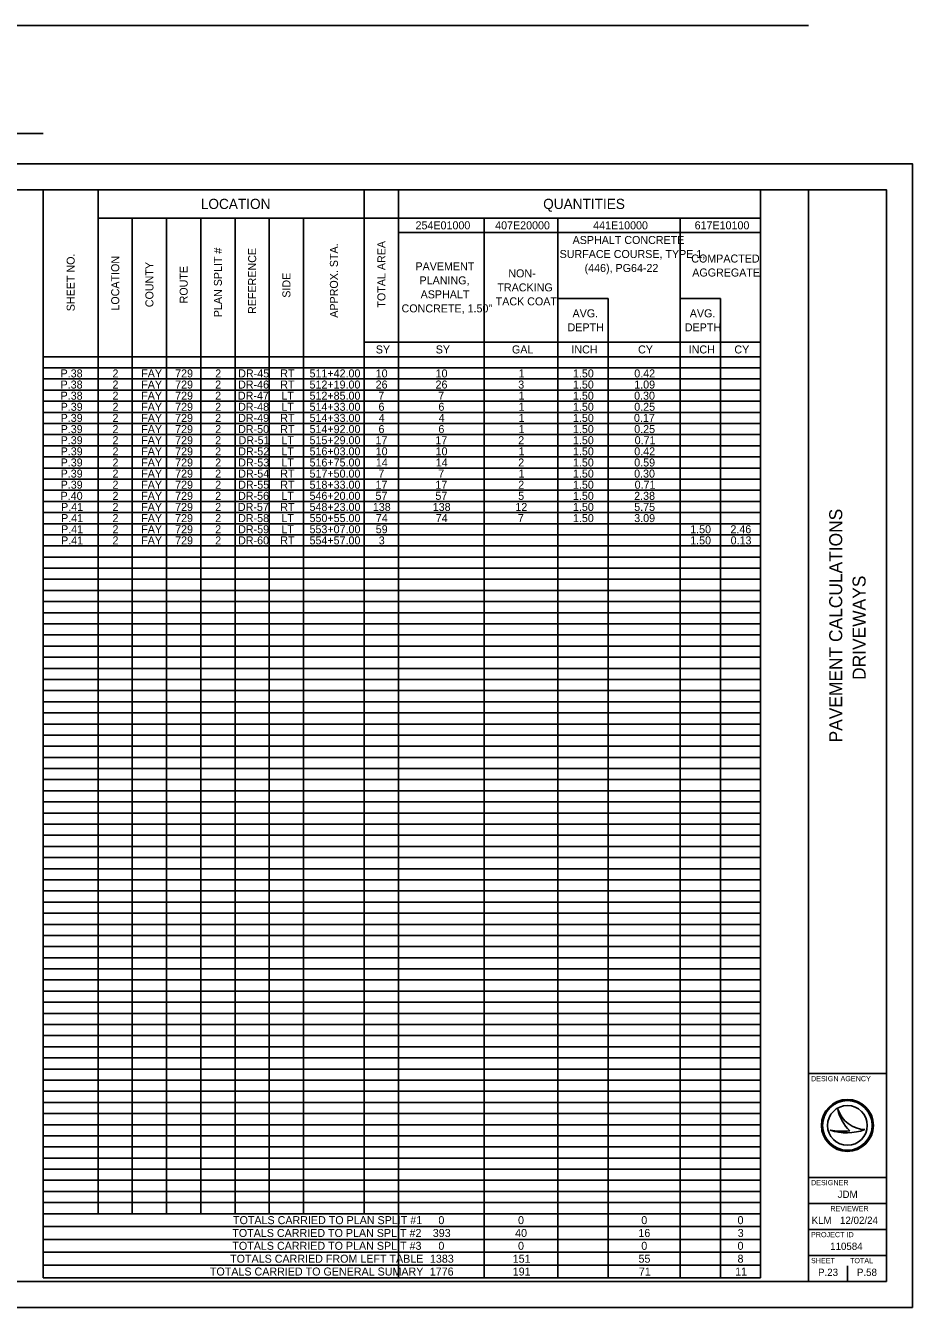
# Model space of a CAD drawing. Extents: x 0 to 34, y 0 to 24.7.
# Drawn here: x 16.94 to 34, y 0 to 24.66 of the extents above; entities that cross this region are included whole.
import ezdxf

# ---------------------------------------------------------------- set-up
doc = ezdxf.new("R2010")
doc.units = 0
for name, color, linetype in [('SH_Border', 7, 'Continuous'), ('SH_Cut_Line', 7, 'Continuous'), ('SH_Data', 7, 'Continuous'), ('SH_Text', 7, 'Continuous')]:
    doc.layers.add(name, color=color, linetype=linetype)

msp = doc.modelspace()

# ---------------------------------------------------------------- linework, layer by layer
at = {"layer": 'SH_Border'}
for p, q in [((32, 0.5), (32, 21.5)), ((32, 4.5), (33.5, 4.5)), ((32, 2.5), (33.5, 2.5)), ((32, 2), (33.5, 2)), ((32, 1.5), (33.5, 1.5)), ((32, 1), (33.5, 1))]:
    msp.add_line(p, q, dxfattribs=at)
msp.add_lwpolyline([(1.5, 21.5), (33.5, 21.5), (33.5, 0.5), (1.5, 0.5)], close=True, dxfattribs=at)
at = {"layer": 'SH_Cut_Line'}
msp.add_lwpolyline([(0, 0), (34, 0), (34, 22), (0, 22)], close=True, dxfattribs=at)
at = {"layer": 'SH_Data'}
for p, q in [((32.567, 3.81), (32.567, 3.81)), ((32.75, 3.5), (32.75, 3.5)), ((32.417, 3.41), (32.417, 3.41)), ((33.087, 3.419), (33.087, 3.419)), ((32.75, 0.5), (32.75, 0.8)), ((32.375, 0.675), (32.375, 0.675))]:
    msp.add_line(p, q, dxfattribs=at)
for radius in [0.5, 0.477, 0.477, 0.382]:
    msp.add_circle((32.75, 3.5), radius, dxfattribs=at)
for centre, radius, start, end in [((33.116, 3.998), 0.58, 198.9257, 198.9319), ((33.347, 3.97), 0.796, 191.6379, 191.6421), ((33.116, 3.998), 0.58, 198.9319, 267.1657), ((33.347, 3.97), 0.796, 191.6421, 226.0947), ((32.739, 4.37), 1.013, 251.4576, 290.0832), ((32.648, 4.654), 1.266, 259.4964, 259.4995), ((32.739, 4.37), 1.013, 251.4527, 251.4576), ((32.648, 4.654), 1.266, 259.4995, 276.6672)]:
    msp.add_arc(centre, radius, start, end, dxfattribs=at)
at = {"layer": 'SH_Text'}
for p, q in [((1.5, 24.657), (32, 24.657)), ((16.223, 22.58), (17.277, 22.58)), ((17.277, 21.5), (31.079, 21.5)), ((17.277, 21.5), (17.277, 0.566)), ((18.331, 21.5), (18.331, 1.801)), ((23.454, 21.5), (23.454, 1.801)), ((24.112, 21.5), (24.112, 0.566)), ((31.079, 21.5), (31.079, 0.566)), ((18.331, 20.956), (31.079, 20.956)), ((18.99, 20.956), (18.99, 1.801)), ((19.649, 20.956), (19.649, 1.801)), ((20.308, 20.956), (20.308, 1.801)), ((20.966, 20.956), (20.966, 1.801)), ((21.625, 20.956), (21.625, 1.801)), ((22.284, 20.956), (22.284, 1.801)), ((25.759, 20.956), (25.759, 1.801)), ((27.176, 20.956), (27.176, 1.801)), ((29.531, 20.956), (29.531, 1.801)), ((24.112, 20.676), (31.079, 20.676)), ((27.176, 19.408), (28.148, 19.408)), ((28.148, 19.408), (28.148, 1.801)), ((29.531, 19.408), (30.305, 19.408)), ((30.305, 19.408), (30.305, 1.801)), ((23.454, 18.568), (31.079, 18.568)), ((17.277, 18.288), (31.079, 18.288)), ((17.277, 18.074), (31.079, 18.074)), ((17.277, 17.86), (31.079, 17.86)), ((17.277, 17.646), (31.079, 17.646)), ((17.277, 17.432), (31.079, 17.432)), ((17.277, 17.218), (31.079, 17.218)), ((17.277, 17.004), (31.079, 17.004)), ((17.277, 16.789), (31.079, 16.789)), ((17.277, 16.575), (31.079, 16.575)), ((17.277, 16.361), (31.079, 16.361)), ((17.277, 16.147), (31.079, 16.147)), ((17.277, 15.933), (31.079, 15.933)), ((17.277, 15.719), (31.079, 15.719)), ((17.277, 15.505), (31.079, 15.505)), ((17.277, 15.291), (31.079, 15.291)), ((17.277, 15.076), (31.079, 15.076)), ((17.277, 14.862), (31.079, 14.862)), ((17.277, 14.648), (31.079, 14.648)), ((17.277, 14.434), (31.079, 14.434)), ((17.277, 14.22), (31.079, 14.22)), ((17.277, 14.006), (31.079, 14.006)), ((17.277, 13.792), (31.079, 13.792)), ((17.277, 13.578), (31.079, 13.578)), ((17.277, 13.364), (31.079, 13.364)), ((17.277, 13.149), (31.079, 13.149)), ((17.277, 12.935), (31.079, 12.935)), ((17.277, 12.721), (31.079, 12.721)), ((17.277, 12.507), (31.079, 12.507)), ((17.277, 12.293), (31.079, 12.293)), ((17.277, 12.079), (31.079, 12.079)), ((17.277, 11.865), (31.079, 11.865)), ((17.277, 11.651), (31.079, 11.651)), ((17.277, 11.436), (31.079, 11.436)), ((17.277, 11.222), (31.079, 11.222)), ((17.277, 11.008), (31.079, 11.008)), ((17.277, 10.794), (31.079, 10.794)), ((17.277, 10.58), (31.079, 10.58)), ((17.277, 10.366), (31.079, 10.366)), ((17.277, 10.152), (31.079, 10.152)), ((17.277, 9.938), (31.079, 9.938)), ((17.277, 9.724), (31.079, 9.724)), ((17.277, 9.509), (31.079, 9.509)), ((17.277, 9.295), (31.079, 9.295)), ((17.277, 9.081), (31.079, 9.081)), ((17.277, 8.867), (31.079, 8.867)), ((17.277, 8.653), (31.079, 8.653)), ((17.277, 8.439), (31.079, 8.439)), ((17.277, 8.225), (31.079, 8.225)), ((17.277, 8.011), (31.079, 8.011)), ((17.277, 7.796), (31.079, 7.796)), ((17.277, 7.582), (31.079, 7.582)), ((17.277, 7.368), (31.079, 7.368)), ((17.277, 7.154), (31.079, 7.154)), ((17.277, 6.94), (31.079, 6.94)), ((17.277, 6.726), (31.079, 6.726)), ((17.277, 6.512), (31.079, 6.512)), ((17.277, 6.298), (31.079, 6.298)), ((17.277, 6.084), (31.079, 6.084)), ((17.277, 5.869), (31.079, 5.869)), ((17.277, 5.655), (31.079, 5.655)), ((17.277, 5.441), (31.079, 5.441)), ((17.277, 5.227), (31.079, 5.227)), ((17.277, 5.013), (31.079, 5.013)), ((17.277, 4.799), (31.079, 4.799)), ((17.277, 4.585), (31.079, 4.585)), ((17.277, 4.371), (31.079, 4.371)), ((17.277, 4.156), (31.079, 4.156)), ((17.277, 3.942), (31.079, 3.942)), ((17.277, 3.728), (31.079, 3.728)), ((17.277, 3.514), (31.079, 3.514)), ((17.277, 3.3), (31.079, 3.3)), ((17.277, 3.086), (31.079, 3.086)), ((17.277, 2.872), (31.079, 2.872)), ((17.277, 2.658), (31.079, 2.658)), ((17.277, 2.444), (31.079, 2.444)), ((17.277, 2.229), (31.079, 2.229)), ((17.277, 2.015), (31.079, 2.015)), ((17.277, 1.801), (31.079, 1.801)), ((25.759, 1.801), (25.759, 0.566)), ((27.176, 1.801), (27.176, 0.566)), ((28.148, 1.801), (28.148, 0.566)), ((29.531, 1.801), (29.531, 0.566)), ((30.305, 1.801), (30.305, 0.566)), ((17.277, 1.554), (31.079, 1.554)), ((17.277, 1.307), (31.079, 1.307)), ((17.277, 1.06), (31.079, 1.06)), ((17.277, 0.813), (31.079, 0.813)), ((17.277, 0.566), (31.079, 0.566))]:
    msp.add_line(p, q, dxfattribs=at)

# ---------------------------------------------------------------- texts
at = {"layer": 'SH_Data'}
for s, p in [('PAVEMENT CALCULATIONS', (32.65, 10.868)), ('DRIVEWAYS', (33.1, 12.071))]:
    msp.add_text(s, height=0.25, rotation=90, dxfattribs=at).set_placement(p)
for s, height, p in [('DESIGN AGENCY', 0.1, (32.05, 4.35)), ('DESIGNER', 0.1, (32.05, 2.35)), ('JDM', 0.14, (32.562, 2.105)), ('KLM', 0.14, (32.061, 1.605)), ('REVIEWER', 0.1, (32.422, 1.85)), ('12/02/24', 0.14, (32.608, 1.605)), ('PROJECT ID', 0.1, (32.05, 1.35)), ('110584', 0.14, (32.418, 1.105)), ('SHEET', 0.1, (32.05, 0.85)), ('P.23', 0.14, (32.185, 0.605)), ('TOTAL', 0.1, (32.8, 0.85)), ('P.58', 0.14, (32.933, 0.605))]:
    msp.add_text(s, height=height, dxfattribs=at).set_placement(p)
at = {"layer": 'SH_Text'}
for s, height, p in [('LOCATION', 0.196, (20.308, 21.13)), ('QUANTITIES', 0.196, (26.896, 21.13)), ('254E01000', 0.154, (24.44, 20.739)), ('407E20000', 0.154, (25.972, 20.739)), ('441E10000', 0.154, (27.858, 20.739)), ('617E10100', 0.154, (29.81, 20.739)), ('ASPHALT CONCRETE ', 0.154, (27.462, 20.457)), ('SURFACE COURSE, TYPE 1, ', 0.154, (27.212, 20.187)), ('COMPACTED ', 0.154, (29.745, 20.1)), ('PAVEMENT ', 0.154, (24.438, 19.95)), ('(446), PG64-22', 0.154, (27.693, 19.918)), ('AGGREGATE', 0.154, (29.764, 19.831)), ('PLANING, ', 0.154, (24.517, 19.68)), ('NON-', 0.154, (26.225, 19.815)), ('ASPHALT ', 0.154, (24.538, 19.411)), ('TRACKING ', 0.154, (26.015, 19.545)), ('CONCRETE, 1.50"', 0.154, (24.171, 19.141)), ('TACK COAT', 0.154, (25.982, 19.276)), ('AVG. ', 0.154, (27.461, 19.046)), ('AVG. ', 0.154, (29.717, 19.046)), ('DEPTH', 0.154, (27.365, 18.776)), ('DEPTH', 0.154, (29.621, 18.776)), ('SY', 0.154, (23.675, 18.351)), ('SY', 0.154, (24.828, 18.351)), ('GAL', 0.154, (26.295, 18.351)), ('INCH', 0.154, (27.439, 18.351)), ('CY', 0.154, (28.722, 18.351)), ('INCH', 0.154, (29.696, 18.351)), ('CY', 0.154, (30.575, 18.351)), ('P.38', 0.154, (17.61, 17.89)), ('2', 0.154, (18.609, 17.89)), ('FAY', 0.154, (19.161, 17.89)), ('729', 0.154, (19.814, 17.89)), ('2', 0.154, (20.585, 17.89)), ('DR-45', 0.154, (21.028, 17.89)), ('RT', 0.154, (21.837, 17.89)), ('511+42.00', 0.154, (22.4, 17.89)), ('10', 0.154, (23.673, 17.89)), ('10', 0.154, (24.826, 17.89)), ('1', 0.154, (26.422, 17.89)), ('1.50', 0.154, (27.469, 17.89)), ('0.42', 0.154, (28.649, 17.89)), ('P.38', 0.154, (17.61, 17.676)), ('2', 0.154, (18.609, 17.676)), ('FAY', 0.154, (19.161, 17.676)), ('729', 0.154, (19.814, 17.676)), ('2', 0.154, (20.585, 17.676)), ('DR-46', 0.154, (21.025, 17.676)), ('RT', 0.154, (21.837, 17.676)), ('512+19.00', 0.154, (22.4, 17.676)), ('26', 0.154, (23.672, 17.676)), ('26', 0.154, (24.825, 17.676)), ('3', 0.154, (26.416, 17.676)), ('1.50', 0.154, (27.469, 17.676)), ('1.09', 0.154, (28.648, 17.676)), ('P.38', 0.154, (17.61, 17.462)), ('2', 0.154, (18.609, 17.462)), ('FAY', 0.154, (19.161, 17.462)), ('729', 0.154, (19.814, 17.462)), ('2', 0.154, (20.585, 17.462)), ('DR-47', 0.154, (21.022, 17.462)), ('LT', 0.154, (21.857, 17.462)), ('512+85.00', 0.154, (22.4, 17.462)), ('7', 0.154, (23.724, 17.462)), ('7', 0.154, (24.877, 17.462)), ('1', 0.154, (26.422, 17.462)), ('1.50', 0.154, (27.469, 17.462)), ('0.30', 0.154, (28.646, 17.462)), ('P.39', 0.154, (17.611, 17.248)), ('2', 0.154, (18.609, 17.248)), ('FAY', 0.154, (19.161, 17.248)), ('729', 0.154, (19.814, 17.248)), ('2', 0.154, (20.585, 17.248)), ('DR-48', 0.154, (21.026, 17.248)), ('LT', 0.154, (21.857, 17.248)), ('514+33.00', 0.154, (22.4, 17.248)), ('6', 0.154, (23.727, 17.248)), ('6', 0.154, (24.88, 17.248)), ('1', 0.154, (26.422, 17.248)), ('1.50', 0.154, (27.469, 17.248)), ('0.25', 0.154, (28.648, 17.248)), ('P.39', 0.154, (17.611, 17.034)), ('2', 0.154, (18.609, 17.034)), ('FAY', 0.154, (19.161, 17.034)), ('729', 0.154, (19.814, 17.034)), ('2', 0.154, (20.585, 17.034)), ('DR-49', 0.154, (21.027, 17.034)), ('RT', 0.154, (21.837, 17.034)), ('514+33.00', 0.154, (22.4, 17.034)), ('4', 0.154, (23.732, 17.034)), ('4', 0.154, (24.885, 17.034)), ('1', 0.154, (26.422, 17.034)), ('1.50', 0.154, (27.469, 17.034)), ('0.17', 0.154, (28.643, 17.034)), ('P.39', 0.154, (17.611, 16.819)), ('2', 0.154, (18.609, 16.819)), ('FAY', 0.154, (19.161, 16.819)), ('729', 0.154, (19.814, 16.819)), ('2', 0.154, (20.585, 16.819)), ('DR-50', 0.154, (21.026, 16.819)), ('RT', 0.154, (21.837, 16.819)), ('514+92.00', 0.154, (22.4, 16.819)), ('6', 0.154, (23.727, 16.819)), ('6', 0.154, (24.88, 16.819)), ('1', 0.154, (26.422, 16.819)), ('1.50', 0.154, (27.469, 16.819)), ('0.25', 0.154, (28.648, 16.819)), ('P.39', 0.154, (17.611, 16.605)), ('P.39', 0.154, (17.611, 16.391)), ('2', 0.154, (18.609, 16.605)), ('2', 0.154, (18.609, 16.391)), ('FAY', 0.154, (19.161, 16.605)), ('FAY', 0.154, (19.161, 16.391)), ('729', 0.154, (19.814, 16.605)), ('729', 0.154, (19.814, 16.391)), ('2', 0.154, (20.585, 16.605)), ('2', 0.154, (20.585, 16.391)), ('DR-52', 0.154, (21.029, 16.391)), ('DR-51', 0.154, (21.035, 16.605)), ('LT', 0.154, (21.857, 16.605)), ('LT', 0.154, (21.857, 16.391)), ('515+29.00', 0.154, (22.4, 16.605)), ('516+03.00', 0.154, (22.4, 16.391)), ('17', 0.154, (23.669, 16.605)), ('10', 0.154, (23.673, 16.391)), ('17', 0.154, (24.822, 16.605)), ('10', 0.154, (24.826, 16.391)), ('2', 0.154, (26.416, 16.605)), ('1', 0.154, (26.422, 16.391)), ('1.50', 0.154, (27.469, 16.605)), ('1.50', 0.154, (27.469, 16.391)), ('0.42', 0.154, (28.649, 16.391)), ('0.71', 0.154, (28.656, 16.605)), ('P.39', 0.154, (17.611, 16.177)), ('2', 0.154, (18.609, 16.177)), ('FAY', 0.154, (19.161, 16.177)), ('729', 0.154, (19.814, 16.177)), ('2', 0.154, (20.585, 16.177)), ('DR-53', 0.154, (21.029, 16.177)), ('LT', 0.154, (21.857, 16.177)), ('516+75.00', 0.154, (22.4, 16.177)), ('14', 0.154, (23.676, 16.177)), ('14', 0.154, (24.829, 16.177)), ('2', 0.154, (26.416, 16.177)), ('1.50', 0.154, (27.469, 16.177)), ('0.59', 0.154, (28.648, 16.177)), ('P.39', 0.154, (17.611, 15.963)), ('2', 0.154, (18.609, 15.963)), ('FAY', 0.154, (19.161, 15.963)), ('729', 0.154, (19.814, 15.963)), ('2', 0.154, (20.585, 15.963)), ('DR-54', 0.154, (21.029, 15.963)), ('RT', 0.154, (21.837, 15.963)), ('517+50.00', 0.154, (22.4, 15.963)), ('7', 0.154, (23.724, 15.963)), ('7', 0.154, (24.877, 15.963)), ('1', 0.154, (26.422, 15.963)), ('1.50', 0.154, (27.469, 15.963)), ('0.30', 0.154, (28.646, 15.963)), ('P.39', 0.154, (17.611, 15.749)), ('2', 0.154, (18.609, 15.749)), ('FAY', 0.154, (19.161, 15.749)), ('729', 0.154, (19.814, 15.749)), ('2', 0.154, (20.585, 15.749)), ('DR-55', 0.154, (21.028, 15.749)), ('RT', 0.154, (21.837, 15.749)), ('518+33.00', 0.154, (22.4, 15.749)), ('17', 0.154, (23.669, 15.749)), ('17', 0.154, (24.822, 15.749)), ('2', 0.154, (26.416, 15.749)), ('1.50', 0.154, (27.469, 15.749)), ('0.71', 0.154, (28.656, 15.749)), ('P.40', 0.154, (17.61, 15.535)), ('2', 0.154, (18.609, 15.535)), ('FAY', 0.154, (19.161, 15.535)), ('729', 0.154, (19.814, 15.535)), ('2', 0.154, (20.585, 15.535)), ('DR-56', 0.154, (21.025, 15.535)), ('LT', 0.154, (21.857, 15.535)), ('546+20.00', 0.154, (22.4, 15.535)), ('57', 0.154, (23.669, 15.535)), ('57', 0.154, (24.822, 15.535)), ('5', 0.154, (26.415, 15.535)), ('1.50', 0.154, (27.469, 15.535)), ('2.38', 0.154, (28.647, 15.535)), ('P.41', 0.154, (17.619, 15.321)), ('2', 0.154, (18.609, 15.321)), ('FAY', 0.154, (19.161, 15.321)), ('729', 0.154, (19.814, 15.321)), ('2', 0.154, (20.585, 15.321)), ('DR-57', 0.154, (21.022, 15.321)), ('RT', 0.154, (21.837, 15.321)), ('548+23.00', 0.154, (22.4, 15.321)), ('138', 0.154, (23.618, 15.321)), ('138', 0.154, (24.771, 15.321)), ('12', 0.154, (26.361, 15.321)), ('1.50', 0.154, (27.469, 15.321)), ('5.75', 0.154, (28.648, 15.321)), ('P.41', 0.154, (17.619, 15.107)), ('P.41', 0.154, (17.619, 14.892)), ('2', 0.154, (18.609, 15.107)), ('2', 0.154, (18.609, 14.892)), ('FAY', 0.154, (19.161, 15.107)), ('FAY', 0.154, (19.161, 14.892)), ('729', 0.154, (19.814, 15.107)), ('729', 0.154, (19.814, 14.892)), ('2', 0.154, (20.585, 15.107)), ('2', 0.154, (20.585, 14.892)), ('DR-58', 0.154, (21.026, 15.107)), ('DR-59', 0.154, (21.027, 14.892)), ('LT', 0.154, (21.857, 15.107)), ('LT', 0.154, (21.857, 14.892)), ('550+55.00', 0.154, (22.4, 15.107)), ('553+07.00', 0.154, (22.4, 14.892)), ('59', 0.154, (23.674, 14.892)), ('74', 0.154, (23.676, 15.107)), ('74', 0.154, (24.829, 15.107)), ('7', 0.154, (26.409, 15.107)), ('1.50', 0.154, (27.469, 15.107)), ('3.09', 0.154, (28.648, 15.107)), ('1.50', 0.154, (29.725, 14.892)), ('2.46', 0.154, (30.499, 14.892)), ('P.41', 0.154, (17.619, 14.678)), ('2', 0.154, (18.609, 14.678)), ('FAY', 0.154, (19.161, 14.678)), ('729', 0.154, (19.814, 14.678)), ('2', 0.154, (20.585, 14.678)), ('DR-60', 0.154, (21.026, 14.678)), ('RT', 0.154, (21.837, 14.678)), ('554+57.00', 0.154, (22.4, 14.678)), ('3', 0.154, (23.732, 14.678)), ('1.50', 0.154, (29.725, 14.678)), ('0.13', 0.154, (30.503, 14.678)), ('TOTALS CARRIED TO PLAN SPLIT #1', 0.154, (20.928, 1.601)), ('0', 0.154, (24.88, 1.601)), ('0', 0.154, (26.412, 1.601)), ('0', 0.154, (28.784, 1.601)), ('0', 0.154, (30.636, 1.601)), ('TOTALS CARRIED TO PLAN SPLIT #2', 0.154, (20.914, 1.354)), ('393', 0.154, (24.772, 1.354)), ('40', 0.154, (26.356, 1.354)), ('16', 0.154, (28.728, 1.354)), ('3', 0.154, (30.639, 1.354)), ('TOTALS CARRIED TO PLAN SPLIT #3', 0.154, (20.915, 1.107)), ('0', 0.154, (24.88, 1.107)), ('0', 0.154, (26.412, 1.107)), ('0', 0.154, (28.784, 1.107)), ('0', 0.154, (30.636, 1.107)), ('TOTALS CARRIED FROM LEFT TABLE', 0.154, (20.872, 0.859)), ('1383', 0.154, (24.717, 0.859)), ('151', 0.154, (26.31, 0.859)), ('55', 0.154, (28.73, 0.859)), ('8', 0.154, (30.636, 0.859)), ('TOTALS CARRIED TO GENERAL SUMARY', 0.154, (20.483, 0.612)), ('1776', 0.154, (24.714, 0.612)), ('191', 0.154, (26.31, 0.612)), ('71', 0.154, (28.737, 0.612)), ('11', 0.154, (30.59, 0.612))]:
    msp.add_text(s, height=height, dxfattribs=at).set_placement(p)
for s, p in [('TOTAL AREA', (23.86, 19.233)), ('SHEET NO.', (17.881, 19.163)), ('PLAN SPLIT #', (20.714, 19.048)), ('REFERENCE', (21.373, 19.111)), ('APPROX. STA.', (22.946, 19.038)), ('LOCATION', (18.738, 19.175)), ('COUNTY', (19.396, 19.241)), ('ROUTE', (20.055, 19.314)), ('SIDE', (22.032, 19.423))]:
    msp.add_text(s, height=0.154, rotation=90, dxfattribs=at).set_placement(p)

doc.saveas('drawing.dxf')
